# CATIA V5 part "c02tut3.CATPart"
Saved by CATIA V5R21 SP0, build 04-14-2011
Part number: c03tut3
Bounding box of the stored display mesh (mm): x 0 to 0, y -40 to 40, z -30 to 30
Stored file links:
  D:\CATIA V5R21 E-RESOURCES\CATIA-V5R21\catia-v5r21-prt\c02-catia-v5r21-prt\catia-v5r21-tut-3.CATPart
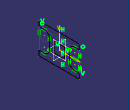
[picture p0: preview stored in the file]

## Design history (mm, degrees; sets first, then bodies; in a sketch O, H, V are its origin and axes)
Body1 (main body)
  Sketch1 on yz-plane, origin (0, 0, 0), H (0, 1, 0), V (0, 0, 1)
    line L1 (-40, -30) -> (40, -30)
    line L2 (40, -30) -> (40, -20)
    line L3 (40, -20) -> (30, -20)
    arc A1 centre (30, -10) radius 10 from (30, -20) to (20, -10) cw
    line L4 (20, -10) -> (20, 10)
    arc A2 centre (30, 10) radius 10 from (20, 10) to (30, 20) cw
    line L5 (30, 20) -> (40, 20)
    point P10 (40, 20)
    line L6 (40, 20) -> (40, 30)
    line L7 (40, 30) -> (-40, 30)
    line L8 (-40, 30) -> (-40, 20)
    point P13 (-40, 20)
    line L9 (-40, 20) -> (-30, 20)
    arc A3 centre (-30, 10) radius 10 from (-30, 20) to (-20, 10) cw
    line L10 (-20, 10) -> (-20, -10)
    arc A4 centre (-30, -10) radius 10 from (-20, -10) to (-30, -20) cw
    line L11 (-30, -20) -> (-40, -20)
    line L12 (-40, -20) -> (-40, -30)
    line L13 (-10, 10) -> (10, 10)
    line L14 (10, 10) -> (10, -10)
    line L15 (10, -10) -> (-10, -10)
    line L16 (-10, -10) -> (-10, 10)
    horizontal: L1 H, L3 H, L7 H, L13 H, L15 H
    vertical: L2 V, L8 V, L14 V, L16 V
    tangency: A1 L2, A1 L3, L4 A1, A2 A1, A2 L4, L5 A2, L6 A2, L9 A2, A3 L8, A3 L9, L10 A3, A4 L3, A4 L10, L11 A4, L12 A3
    coincidence: P10 L2, P13 L5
